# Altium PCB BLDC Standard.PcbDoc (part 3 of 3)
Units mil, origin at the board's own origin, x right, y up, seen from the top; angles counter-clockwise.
Board outline 4950 x 3000 mil, 4 copper layers (Top Layer, MidLayer1, MidLayer2, Bottom Layer), stack 63.4 mil thick; 211 components, 117 nets, 576 pads, 1027 vias.
Unrouted connection lines stored in the file: 2.
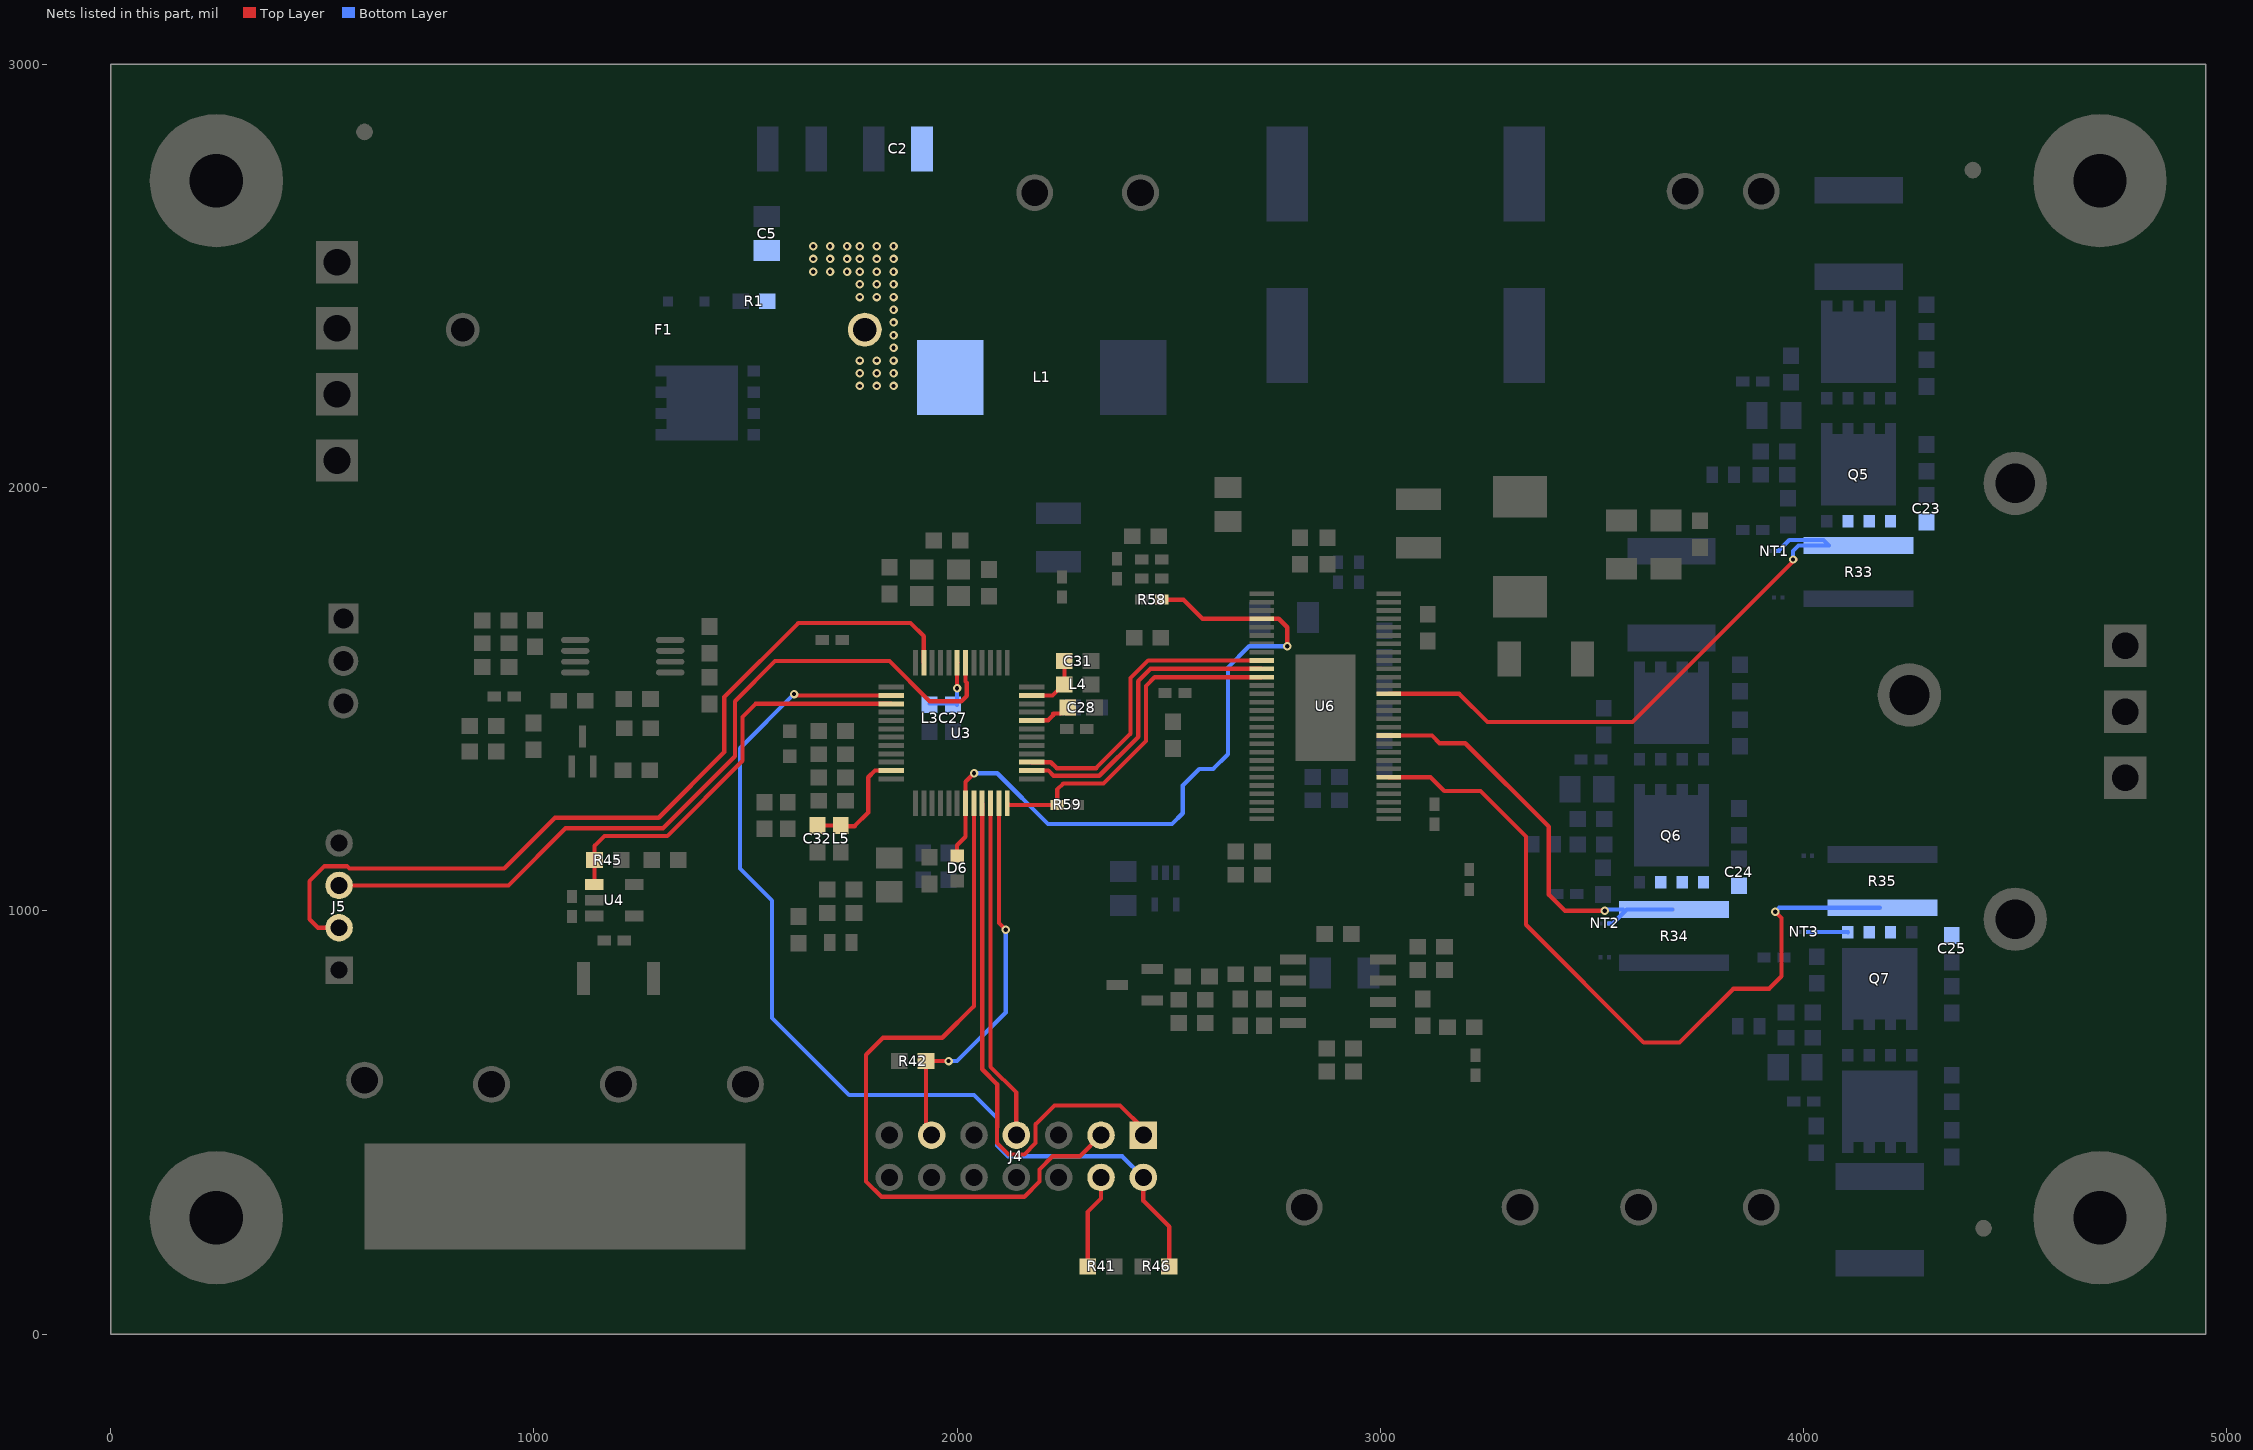
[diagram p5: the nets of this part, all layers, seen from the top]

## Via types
v1: diameter 20, hole 10, Top Layer to Bottom Layer, 1027 vias

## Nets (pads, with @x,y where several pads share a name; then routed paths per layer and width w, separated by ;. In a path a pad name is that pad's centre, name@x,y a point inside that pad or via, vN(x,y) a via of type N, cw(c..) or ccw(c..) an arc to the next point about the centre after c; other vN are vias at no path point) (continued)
PWRGD: D6.1 R58.1 U3.19 U6.4 | length 1702.5
  Top Layer w10: D6.1@2000,1129.53 2000,1155 2020,1175 U3.19@2020,1254 2020,1305 v1(2040,1325) ; R58.1@2483.62,1735 2535,1735 2580.09,1689.91 U6.4@2719.92,1689.91 2760.09,1689.91 2780,1670 v1(2780,1625)
  Bottom Layer w10: v1(2040,1325) 2095,1325 2215,1205 2507.53,1205 2533,1230.47 2533,1296 2572,1335 2605,1335 2640,1370 2640,1575 2690,1625 v1(2780,1625)
RESETN: R45.1 U3.3 U4.1 | length 991.6
  Top Layer w10: U4.1@1142.76,1062.4 1143.5,1063.15 R45.1@1143.5,1120 1143.5,1153.5 1167,1177 1315.46,1177 1493,1354.54 1493,1458 1524,1489 U3.3@1844.1,1489
SCIRXDA: J5.3 U3.42 | length 1902.6
  Top Layer w10: J5.3@540,1060 940,1060 1075,1195 1305,1195 1475,1365 1475,1495 1570,1590 1840,1590 1935,1495 2010,1495 2023,1508 2023,1538.55 2020,1541.55 U3.42@2020,1585.9
SCITXDA: J5.2 U3.47 | length 2028.8
  Top Layer w10: J5.2@540,960 490,960 470,980 470,1070 505.48,1105.48 558.84,1105.48 564.32,1100 930,1100 1050,1220 1295,1220 1450,1375 1450,1505 1625,1680 1890,1680 1921.5,1648.5 U3.47@1921.5,1585.9
SCLK: R59.2 U3.24 U6.11 | length 825.6
  Top Layer w10: U3.24@2118.5,1254 2122.5,1250 R59.2@2236.38,1250 2236.38,1286.38 2251,1301 2346,1301 2446,1401 2446,1531 2467.01,1552.01 U6.11@2719.92,1552.01
SDI: U3.27 U6.9 | length 732.1
  Top Layer w10: U3.27@2176.1,1351.1 2221.37,1351.1 2235.47,1337 2328.54,1337 2410,1418.46 2410,1550 2451.41,1591.41 U6.9@2719.92,1591.41
SDO: U3.26 U6.10 | length 730.7
  Top Layer w10: U3.26@2176.1,1331.4 2215.62,1331.4 2228.02,1319 2336,1319 2428,1411 2428,1542.54 2457.17,1571.71 U6.10@2719.92,1571.71
SL_A: C23.2 NT1.1 Q5.1 Q5.2 Q5.3 R33.2 U6.44 | length 1393.3
  Top Layer w10: U6.44@3019.92,1512.61 3186.48,1512.61 3253.09,1446 3596,1446 v1@3980,1830
  Bottom Layer w10: NT1.1@3940,1850 3966,1876 4046.99,1876 4060,1862.99 3987.99,1862.99 3975,1850 v1(3975,1830)
SL_B: C24.2 NT2.1 Q6.1 Q6.2 Q6.3 R34.2 U6.39 | length 983.5
  Top Layer w10: U6.39@3019.92,1414.11 3121.89,1414.11 3140,1396 3200.46,1396 3398,1198.46 3398,1038 3436,1000 v1(3530,1000)
  Bottom Layer w10: v1(3530,1000) 3532.99,1002.99 R34.2@3572.99,1002.99 ; NT2.1@3540,970 3549,970 3581.99,1002.99 R34.2@3690,1002.99
SL_C: C25.2 NT3.1 Q7.1 Q7.2 Q7.3 R35.2 U6.34 | length 1878.9
  Top Layer w10: U6.34@3019.92,1315.61 3118.39,1315.61 3151.04,1282.96 3236.59,1282.96 3344,1175.54 3344,967 3622,689 3706.98,689 3833.96,815.98 3918.51,815.98 3948,845.47 3948,983 v1(3933,998)
  Bottom Layer w10: v1(3933,998) 3942.01,1007.01 R35.2@4180,1007.01 ; NT3.1@4010,950 4103.81,950 Q7.1@4104.51,949.3
TCK: J4.11 R42.2 U3.23 | length 917.4
  Top Layer w10: J4.11@1940,470 1926.5,483.5 R42.2@1926.5,645 v1(1980,645) ; U3.23@2098.8,1254 2098.8,971.2 v1(2115,955)
  Bottom Layer w10: v1(1980,645) 2000,645 2115,760 v1(2115,955)
TDI: J4.3 U3.20 | length 1727.8
  Top Layer w10: U3.20@2039.7,1254 2039.7,774.7 1965,700 1825,700 1785,660 1785,360.68 1821.16,324.52 2158.84,324.52 2194.52,360.2 2194.52,388.84 2225.68,420 2290,420 J4.3@2340,470
TDIS: J4.4 R41.2 | length 223
  Top Layer w10: R41.2@2308.5,160 2308.5,288.5 2340,320 J4.4@2340,370
TDO: J4.7 U3.22 | length 809.2
  Top Layer w10: U3.22@2079.1,1254 2079.1,631.36 2140,570.46 J4.7@2140,470
TMS: J4.1 U3.21 | length 1285.9
  Top Layer w10: U3.21@2059.4,1254 2059.4,625.6 2095,590 2095,489.32 2094.52,488.84 2094.52,451.16 2121.16,424.52 2158.84,424.52 2185.48,451.16 2185.48,495.48 2230,540 2385,540 2440,485 J4.1@2440,470
TRSTN: J4.2 R46.2 U3.2 | length 2386.6
  Top Layer w10: v1(1615,1512) 1618.3,1508.7 U3.2@1844.1,1508.7 ; J4.2@2440,370 2440,315 2501.5,253.5 R46.2@2501.5,160
  Bottom Layer w10: v1(1615,1512) 1487,1384 1487,1100 1563,1024 1563,747 1745,565 2040,565 2094.52,510.48 2094.52,445.68 2120.2,420 2390,420 J4.2@2440,370
VBATT: C2.1 C5.1 F1.2 L1.1 R1.2
  other v1: 1770,2240 1810,2240 1850,2240 1770,2270 1810,2270 1850,2270 1770,2300 1810,2300 1850,2300 1850,2330 1850,2360 1850,2390 1850,2420 1770,2450 1810,2450 1850,2450 1770,2480 1810,2480 1850,2480 1660,2510 1700,2510 1740,2510 1770,2510 1810,2510 1850,2510 1660,2540 1700,2540 1740,2540 1770,2540 1810,2540 1850,2540 1660,2570 1700,2570 1740,2570 1770,2570 1810,2570 1850,2570
VDD: C28.1 U3.32 | length 93.3
  Top Layer w10: U3.32@2176.1,1449.6 2176.89,1450.39 2215.39,1450.39 2227,1462 ; 2227,1466 2244.5,1466 C28.1@2258.5,1480
VDD_1: C27.1 L3.2 U3.43 | length 164.5
  Top Layer w10: v1(2000,1526.02) 2000,1585.6 U3.43@2000.3,1585.9
  Bottom Layer w10: L3.2@1935,1489.45 C27.1@2000,1489.45 ; C27.1@2000,1486.5 C27.1@2000,1489.45 ; v1(2000,1526.02) C27.1@2000,1489.45
VDDA: C32.1 L5.2 U3.11 | length 266
  Top Layer w10: C32.1@1670,1201.5 L5.2@1725,1201.5 ; L5.2@1736.5,1200 1758,1200 1790,1232 1790,1315.54 1805.86,1331.4 U3.11@1844.1,1331.4
VDDIO_2: C31.1 L4.2 U3.35 | length 143.3
  Top Layer w10: U3.35@2176.1,1508.7 2225.43,1508.7 2251.73,1535 L4.2@2253.5,1535 C31.1@2253.5,1590
pads on no net: FID1.1 FID2.1 FID3.1 H1.0 H2.0 H3.1 H4.1 H5.0 H6.0 H7.1 H8.1 J4.6 J4.13 J4.14 LBL1.0 Logo1.0 U2.3 U3.30 U4.4 Y1.2 Y1.4

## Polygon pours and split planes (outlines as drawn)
3P3V on MidLayer2 "GND" (solid, remove dead copper, pour order 2): 450,1110 1000,1110 1000,300 2295,300 2300,305 2300,800 3150,800 3150,1930 450,1930
DC+ on MidLayer2 "GND" (solid, remove dead copper, pour order 8): 2532,2740 2296,2740 2296,2559 2085,2559 2085,1940 3160,1940 3160,180 3162.79,182.79 4427.21,182.79 4427.21,567.21 4430,570 4280,570 4280,630 4070,630 4070,720 3980,720 3980,860 4069.96,860 4069.96,929.96 4070,930 4380,930 4380,1138.71 4378.71,1140 3820,1140 3820,1080 3580,1080 3580,1040 3490,1040 3490,1389.8 3489.8,1390 3780,1390 3780,1550 3890,1550 3890,2060 4020,2060 4020,2237.57 4022.63,2240.2 4219.8,2240.2 4219.8,2399.8 4220,2400 4330,2400 4330,2570 2532,2570
GND on MidLayer1 "GND" (solid, remove dead copper, pour order 5): 20,2980 20,20 4930,20 4930,2980
GND on Bottom Layer "GND" (solid, remove dead copper, pour order 6): 20,2980 20,20 4930,20 4930,2980
DC+ on Bottom Layer "GND" (solid, remove dead copper, pour order 4): 2102.37,2770 2102.04,1962.15 3200,1960 3200,1237.8 2899,951.85 2899,190 4420,190 4420,440 4280,440 4280,630 4080,630 4080,450 3945,450 3690,705 3650,670 3470,850 3470,1390 3780,1390 3780,1550 3890,1550 3890,2290 4020,2290 4020,2240 4220,2240 4220,2400 4330,2400 4330,2570 2600,2570 2600,2770
GND on Top Layer "GND" (solid, remove dead copper, pour order 7): -57.39,2924.28 -57.39,-35.72 4852.61,-35.72 4852.61,2924.28

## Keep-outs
Keep-Out Layer:
  text ".Layer_Name" at 577,-858.49 h60

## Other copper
Top Layer:
  pour cut-out: 3635,580 3630,580 3630,587 3273,944 3273,950 3293,970 3622,641 3635,641
  region net VBATT: 1500,2590 1500,2510 1530,2510 1530,2420 1605,2420 1645,2380 1645,2160 2041,2160 2087,2206 2087,2720 1970,2720 1970,2870 1880,2870 1880,2592.44 1882.44,2590
  region net GND: 1485,2590 1235,2590 1235,2315 1495,2315 1495,2150 1600,2150 1600,2380 1375,2380 1375,2480 1485,2480
  region net NetF1_1: 480,2460 480,2160 1140,2160 1140,2530 840,2530 840,2460
  region net BATT_GND: 480,2480 820,2480 820,2550 1160,2550 1160,2140 480,2140 480,2000 1480,2000 1480,2290 1465,2305 1225,2305 1225,2600 1600,2600 1600,2870 1440,2870 1440,2710 480,2710
  pour cut-out: 1068.9,1380.1 1069,1380 1069,1360 1045,1360 1039,1366 1039,1394 1036,1394 1031,1399 1031,1420 1044,1420 1068.9,1444.9
  pour cut-out: 1985,1556 1970,1556 1970,1552 1912,1552 1911,1553 1910,1552 1910,1541 1941,1510 1985,1510
  pour cut-out: 1874.13,1713.39 1874,1713.25 1874,1700 1893,1700 1911.05,1681.95 1920.81,1681.95 1920.81,1704.88 1918.69,1707 1879,1707
  pour cut-out: 1701.81,1458.7 1701.81,1468.81 1702,1469 1702.45,1468.55 1745.22,1468.55 1745.22,1460.52 1743.4,1458.7
  pour cut-out: 1148.07,894.37 1150,896.3 1150,905 1140,905 1130,895
  pour cut-out: 1116.81,959.8 1116.81,936.46 1117.22,936.05 1121.16,940 1140,940 1140,960
  pour cut-out: 1275,1035 1275,1015 1220,1015 1220,1035
  pour cut-out: 585,1040 585,955 560,980 490,980 490,1055
  pour cut-out: 450,1135 450,1075 460,1075 510,1125 510,1135
  pour cut-out: 4285.79,628.34 4220,565 4285,565
  pour cut-out: 1900.44,427.82 1877.62,405 1807.07,405 1805.39,406.68 1805.39,433.32 1870.44,433.32 1881.55,444.43
  pour cut-out: 2487.48,517.48 2157.52,517.48 2155,520 2155,410 2175,390 2170,385 2170,305 2490,305
  pour cut-out: 3193.7,763.44 3277.72,763.44 3206.55,834.61 3186.18,834.61 3186.18,826.18 3193.7,826.18
  pour cut-out: 2839.21,758.19 2853.11,758.19 2853.11,788.05 2841.98,799.18 2840.84,798.03 2839.21,798.03
  pour cut-out: 3110,955 3080,985 2895,985 2895,965 3050,965 3050,955
  pour cut-out: 2934.61,1783.82 2908.7,1783.82 2910,1785.12 2910,1850 2940,1850
  pour cut-out: 3880,1780 3900,1780 3900,1770 3590,1460 3580,1470 3580,1480
  region net DGND: 2350,1640 2295,1640 2295,1570 2350,1570
  region net GND: 2830,750 2650,750 2650,670 2755,670 2755,710 2830,710
  region net GND: 2435,880 2435,825 2555,825 2550,830 2550,880
  region net 3P3V: 2910,965 2910,925 2955,925 2970,910 2970,870 3050,870 3050,965
  region net GND: 3775,1880 3710,1880 3710,1865 3515,1865 3515,1780 3730,1780 3760,1810 3775,1810
  region net 3P3V: 3610,1895 3250,1895 3170,1815 3015,1815 3015,1905 3150,1905 3165,1920 3165,2050 3610,2050
  region net GND: 2750,1222 2692,1222 2692,1070 2749.98,1070
  region net GND: 2435,1917 2360,1917 2360,1810 2455,1810 2455,1845 2435,1845
  region net GND: 1692.5,1445 1557.5,1445 1557.5,1405 1692.5,1405
  region net GND: 1870,1070 1805,1070 1805,985 1870,985
  region net 3P3V: 1715,945 1600,945 1600,880 1715,880
  region net GND: 1065,1570 1065,1530 1100,1530 1100,1440 1065,1440 1065,1380 1125,1380 1125,1450 1145,1450 1145,1570
  region net GND: 1330,880 1270,880 1270,800 1330,800
  region net 3P3V: 1300,1150 1180,1150 1180.16,1149.84 1180.16,1050 1300,1050
  region net C_PHASE: 4900,1380 4390,1380 4390,790 4300,790 4300,920 4080,920 4080,850 3990,850 3990,730 4080,730 4080,640 4230,640 4230,700 4306,700 4306,580 4900,580
  region net B_PHASE: 4900,1540 4400,1540 4400,1640 3900,1640 3900,1410 3790,1410 3790,1380 3640,1380 3640,1310 3570,1310 3570,1180 3500,1180 3500,1080 3560,1080 3560,1100 3797.83,1100 3797.83,1210 4370,1210 4370,1400 4900,1400
  region net A_PHASE: 4080,2230 4080,2160 4030,2160 4030,2050 3940,2050 3940,1950 4230,1950 4230,2070 4340,2070 4340,1660 4420,1660 4420,1560 4900,1560 4900,2230 4370,2230 4370,2260 4230,2260 4230,2230
  region net NetC43_1: 3087,1660 3087,1620 3270,1620 3270,1555 3370,1555 3370,1800 3250,1800 3250,1660
  region net DC+: 3630,1970 3630,1890 3780,1890 3780,1970
  region net DC+: 3057,1720 3075,1720 3075,1695 3065,1685 3057,1685
  text ".CopyrightYear" at 532,90 h60
  text "TI" at 808,90 h60
  text "©" at 414,83 h105
  text ".Layer_Name" at 577,-858.49 h60
MidLayer1:
  text ".Layer_Name" at 577,-858.49 h60
MidLayer2:
  region net DGND: 2032.35,1499.43 1955,1499.43 1955,1380 2195,1380 2195,1495 2295,1495 2295,1460 2365,1460 2365,1475 2390,1475 2390,1515 2335,1515 2335,1555 2355,1555 2355,1635 2170,1635 2170,1515 2155,1500 2045,1500
  region net C_PHASE: 4900,1380 4390,1380 4390,790 4300,790 4300,920 4080,920 4080,850 3990,850 3990,730 4080,730 4080,640 4230,640 4230,700 4306,700 4306,580 4900,580
  region net B_PHASE: 4900,1540 4400,1540 4400,1640 3900,1640 3900,1410 3790,1410 3790,1380 3640,1380 3640,1310 3570,1310 3570,1180 3500,1180 3500,1080 3560,1080 3560,1100 3797.83,1100 3797.83,1210 4370,1210 4370,1400 4900,1400
  region net A_PHASE: 4080,2230 4080,2160 4030,2160 4030,2050 3940,2050 3940,1950 4230,1950 4230,2070 4340,2070 4340,1660 4420,1660 4420,1560 4900,1560 4900,2230 4370,2230 4370,2260 4230,2260 4230,2230
  text ".Layer_Name" at 577,-858.49 h60
Bottom Layer:
  region net VBATT: 1500,2590 1500,2510 1530,2510 1530,2420 1605,2420 1645,2380 1645,2160 2041,2160 2087,2206 2087,2720 1970,2720 1970,2870 1880,2870 1880,2592.44 1882.44,2590
  region net BATT_GND: 480,2480 820,2480 820,2550 1160,2550 1160,2140 480,2140 480,2000 1480,2000 1480,2290 1465,2305 1225,2305 1225,2600 1600,2600 1600,2870 1440,2870 1440,2710 480,2710
  region net DC+: 880,1400 880,1330 1050,1330 1050,1400
  region net NetF1_1: 480,2460 480,2160 1140,2160 1140,2530 840,2530 840,2460
  region net GND: 4265,2800 3800,2800 3800,2600 4265,2600
  region net GND: 4290,210 4060,210 4060,70 4290,70
  region net GND: 4270,1790 4000,1790 4000,1665 4270,1665
  region net GND: 4045,1200 4045,1070 4375,1070 4375,1200
  region net GND: 3555,935 3555,810 3770,810 3785,825 3785,835 3830,835 3830,935
  region net GND: 2105,2595 2105,2945 3600,2945 3600,2600 2520,2600 2520,2805 2305,2805 2305,2595
  region net GND: 2890,965 2845,965 2845,895 2825,895 2825,815 2890,815
  region net GND: 2500,1107.56 2427.32,1107.56 2427.32,1117.56 2337.32,1117.56 2337.32,1067.56 2432.32,1067.56 2432.32,1072.56 2500,1072.56
  region net GND: 2293.15,1861 2183.15,1861 2183.15,1786 2293.15,1786
  region net GND: 1485,2590 1235,2590 1235,2315 1495,2315 1495,2150 1600,2150 1600,2380 1375,2380 1375,2480 1485,2480
  region net C_PHASE: 4900,1380 4390,1380 4390,790 4300,790 4300,920 4080,920 4080,850 3990,850 3990,730 4080,730 4080,640 4230,640 4230,700 4306,700 4306,580 4900,580
  region net B_PHASE: 4900,1540 4400,1540 4400,1640 3900,1640 3900,1410 3790,1410 3790,1380 3640,1380 3640,1310 3570,1310 3570,1180 3500,1180 3500,1080 3560,1080 3560,1100 3797.83,1100 3797.83,1210 4370,1210 4370,1400 4900,1400
  region net A_PHASE: 4080,2230 4080,2160 4030,2160 4030,2050 3940,2050 3940,1950 4230,1950 4230,2070 4340,2070 4340,1660 4420,1660 4420,1560 4900,1560 4900,2230 4370,2230 4370,2260 4230,2260 4230,2230
  region net 3P3V: 2322.32,1047.56 2322.32,987.56 2532.32,987.56 2532.32,1047.56
  region net SL_A: 4310,1940 4080,1940 4080,1890 4000,1890 4000,1820 4310,1820
  region net NetC2_2: 1630,2870 1630,2660 1840,2660 1840,2870
  region net SL_C: 4370,920 4370,1040 4040,1040 4040,930 4220,930 4220,980 4320,980 4320,920
  region net B_V_ADC: 3490,1320 3490,1140 3400,1140 3400,1290 3430,1320
  region net NetC12_2: 3500,1440 3500,1340 3630,1340 3630,1370 3560,1370 3560,1440
  region net SL_B: 3640,1090 3870,1090 3870,980 3566.05,980 3566.05,1023 3640,1023
  region net C_V_ADC: 3977,783 3977,593 3877,593 3877,783
  text ".VersionControl_RevNumber" at 1970,170 h60
  text "MADE IN U.S." at 1967,111 h60
  text "UL94V-0" at 1605,110 h60
  text "SVN:" at 1970,54 h60
  text ".Layer_Name" at 577,-858.49 h60

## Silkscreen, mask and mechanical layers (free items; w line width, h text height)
Top Overlay:
  text "A VOLT" at 3613,2782 h60
  text "DC+" at 2397,2780 h60
  text "GND" at 3852,2780 h60
  text "GND" at 2126,2779 h60
  text "GND" at 550,680 h60
  text "B CURR" at 800,670 h60
  text "DC VOLT" at 1100,670 h60
  text "A CURR" at 1400,670 h60
  text "ADC REF" at 2710,380 h60
  text "C CURR" at 3230,380 h60
  text "B VOLT" at 3510,380 h60
  text "C VOLT" at 3810,380 h60
  text ".Layer_Name" at 577,-858.49 h60
Bottom Overlay:
  region: 65,1691 65,1391 165,1391 165,1691
  text ".PRJ_Number" at 75,725 h60 r270
  text ".PCB_Rev" at 175,725 h60 r270
  text ".Layer_Name" at 577,-858.49 h60
Top Paste:
  text ".Layer_Name" at 577,-858.49 h60
Bottom Paste:
  text ".Layer_Name" at 577,-858.49 h60
Top Solder:
  text ".Layer_Name" at 577,-858.49 h60
  text ".Layer_Name" at 577,-858.49 h60
Bottom Solder:
  text ".Layer_Name" at 577,-858.49 h60
Drill Guide:
  text ".Layer_Name" at 577,-858.49 h60
M1 Board Outline:
  the board outline again, w10
  text ".Layer_Name" at 577,-858.49 h60
M2 Board Dimensions:
  rectangle: 124.5,-410.5 499.5,-285.5
  rectangle: -0.5,-285.5 124.5,-160.5
  lines w7: -0.5,-285.5 999.5,-285.5 ; 124.5,-410.5 124.5,-160.5 ; 249.5,-410.5 249.5,-160.5 ; 499.5,-410.5 499.5,-160.5 ; 749.5,-410.5 749.5,-160.5 ; -0.5,-410.5 -0.5,-160.5 999.5,-160.5 999.5,-410.5 -0.5,-410.5
  lines w10: -0.5,-475.5 -0.5,-455.5 ; 59.5,-485.5 -0.5,-465.5 ; 59.5,-445.5 -0.5,-465.5 ; 223.58,-465.5 -0.5,-465.5 ; 775.42,-465.5 999.5,-465.5 ; 939.5,-485.5 999.5,-465.5 ; 939.5,-445.5 999.5,-465.5 ; 999.5,-475.5 999.5,-455.5
  text "1000 (mil)" at 233.58,-501.49 h60
  text ".Layer_Name" at 577,-858.49 h60
M3 3D STEP Top:
  text ".Layer_Name" at 577,-858.49 h60
M4 3D STEP Bottom:
  text ".Layer_Name" at 577,-858.49 h60
M5 Assembly Top:
  lines w10: -292,-930.17 6308,-930.17 ; -292,-726.83 6310,-726.83 ; -292,-523.5 -292,-1133.5 3713,-1133.5 6310,-1133.5 6310,-523.5 -291.5,-523.5 -291.5,-1133.5 1284,-1133.5 ; 2173,-1133.5 2173,-523.5 ; 3440,-726.83 3440,-523.5 ; 4280,-726.83 4280,-523.5 ; 4902,-1140 4902,-937.17
  text "COMPONENTS MARKED 'DNP' SHOULD NOT BE POPULATED." at 1153.5,-318.5 h60
  text "ASSEMBLY VARIANT:" at 1153,-434 h60
  text ".VariantName" at 2189,-434 h60
  text "PCB VIEWED FROM TOP SIDE" at -228.5,-655.67 h60
  text "BOARD #:" at 2248,-655.67 h60
  text ".PRJ_Number" at 2793.5,-655.67 h60
  text "REV:" at 3638,-655.67 h60
  text ".PCB_Rev" at 3929.5,-655.67 h60
  text "SVN REV:" at 4476,-655.67 h60
  text ".VersionControl_RevNumber" at 4982,-655.67 h60
  text "IGNORE ->" at -228.5,-858.49 h60
  text "PLOT NAME =" at -228.5,-1064.34 h60
  text ".plot_File_Name" at 577,-1064.34 h60
  text "GENERATED    :" at 2250,-1064.34 h60
  text ".Print_Date" at 3119.5,-1064.34 h60
  text ".Print_Time" at 3848.5,-1064.34 h60
  text "TEXAS INSTRUMENTS" at 5113,-1064.34 h60
M6 Assembly Bottom:
  lines w10: -292.5,-727.33 6309.5,-727.33 ; -290.5,-930.67 6309.5,-930.67 ; 1115.5,-1140.5 1115.5,-937.67 ; 1737.5,-727.33 1737.5,-524 ; 2577.5,-727.33 2577.5,-524 ; 3844.5,-1134 3844.5,-524 ; 4733.5,-1134 6309,-1134 6309,-524 -292.5,-524 -292.5,-1134 2304.5,-1134 6309.5,-1134 6309.5,-524
  text "COMPONENTS MARKED 'DNP' SHOULD NOT BE POPULATED." at 6102,-318 h60
  text ".VariantName" at 5058,-434 h60
  text "ASSEMBLY VARIANT:" at 6097,-434 h60
  text ".VersionControl_RevNumber" at 1035.5,-656.17 h60
  text "SVN REV:" at 1541.5,-656.17 h60
  text ".PCB_Rev" at 2088,-656.17 h60
  text "REV:" at 2379.5,-656.17 h60
  text ".PRJ_Number" at 3224,-656.17 h60
  text "BOARD #:" at 3769.5,-656.17 h60
  text "PCB VIEWED FROM BOTTOM SIDE" at 6246,-656.17 h60
  text "IGNORE ->" at 2547.85,-858.49 h60
  text "TEXAS INSTRUMENTS" at 904.5,-1064.84 h60
  text ".Print_Time" at 2169,-1064.84 h60
  text ".Print_Date" at 2898,-1064.84 h60
  text "GENERATED    :" at 3767.5,-1064.84 h60
  text ".plot_File_Name" at 5440.5,-1064.84 h60
  text "PLOT NAME =" at 6246,-1064.84 h60
M9 Title Sheet:
  drawing of 55 lines, arcs and shapes, not listed
  text "1" at 739.84,8036.5 h70
  text "2" at 3235.5,8036.5 h70
  text "3" at 5724.84,8036.5 h70
  text "4" at 8231.51,8036.5 h70
  text "5" at 10730.5,8036.5 h70
  text "6" at 13235.5,8036.5 h70
  text "A" at -416.5,6893.5 h70
  text "A" at 14383.5,6893.5 h70
  text "B" at -416.5,4513.5 h70
  text "B" at 14383.5,4513.5 h70
  text "C" at -416.5,2138.5 h70
  text "PROJECT TITLE:" at 11340,290 h45
  text ".PRJ_Title" at 11393.5,144.17 h70
  text "DESIGNED FOR:" at 11343.5,-23.5 h45
  text ".PRJ_Customer" at 11393.5,-163.5 h70
  text "D" at -416.5,-231.5 h70
  text "D" at 14383.5,-231.5 h70
  text "FILE NAME:" at 11343.5,-323.5 h45
  text ".PCB_File_Name_No_Path" at 11393.5,-443.5 h70
  text "Texas Instruments (TI) and/or its licensors do not warrant the accuracy or completeness of this specification" at 6374,-605.34 h45
  text "ENGINEER:" at 11343.5,-613.5 h45
  text "LAYOUT BY:" at 12848.5,-613.5 h45
  text "or any information contained therein. TI and/or its licensors do not warrant that this design will meet" at 6329.01,-718 h45
  text ".PRJ_Engineer" at 11393.5,-768.49 h70
  text ".PCB_Layout" at 12899,-768.49 h70
  text "the specifications, will be suitable for your application or fit for any particular purpose, or will operate in" at 6329.01,-830.67 h45
  text ".Layer_Name" at 577,-858.49 h60
  text "ALTIUM DESIGNER VERSION:" at 12848.5,-923.5 h45
  text "an implementation. TI and/or its licensors do not warrant that the design is production worthy. You should" at 6329.01,-943.33 h45
  text "completely validate and test your design implementation to confirm the system functionality for your application." at 6374,-1056 h45
  text ".print_Scale" at 11393.5,-1056.83 h70
  text ".Application_BuildNumber" at 12899,-1056.83 h70
  text "1" at 739.84,-1263.5 h70
  text "2" at 3235.5,-1263.5 h70
  text "3" at 5724.84,-1263.5 h70
  text "4" at 8231.51,-1263.5 h70
  text "5" at 10730.5,-1263.5 h70
  text "6" at 13235.5,-1263.5 h70
M10 Fab Notes:
  drawing of 203 lines, arcs and shapes, not listed
  text "DESIGN INFORMATION" at 12377.02,6803 h60
  text "(REFER ALSO ARRAY/PANEL PROFILING INFORMATION)" at 12015.46,6641.29 h60
  text "BOARD SIZE" at 11329.46,6637 h60
  text "3450MIL" at 11791.78,6509.18 h60
  text "X" at 12297.46,6509.18 h60
  text "4950MIL" at 12528.78,6509.18 h60
  text "Number of Layers :" at 11732.46,6312 h60
  text "4" at 12827.27,6302 h60
  text "MIN. TRACK WIDTH:" at 11732.46,6173 h60
  text "8" at 12828.7,6173 h60
  text "MIL" at 12983.46,6173 h60
  text "MIN. CLEARANCE:" at 11732.46,6041 h60
  text "8" at 12828.7,6041 h60
  text "MIL" at 12983.46,6041 h60
  text "MIN. VIA PAD SIZE:" at 11732.46,5909 h60
  text "20" at 12798.71,5909 h60
  text "MIL" at 12983.46,5909 h60
  text "0.05mm (2MIL)" at 12427.46,5767.29 h60
  text "MINIMUM ANNULAR RING" at 11403.23,5763 h60
  text "EXTERNAL" at 13135.46,5763 h60
  text "PER" at 11603.23,5645 h60
  text "IPC-D-275 CLASS 2 LEVEL C" at 11823.23,5645 h60
  text "MIL, HOLES" at 13311.46,5532.71 h60
  text "+/-" at 12919,5532 h60
  text "+/-" at 13773,5532 h60
  text "REGISTRATION TOLERANCES:" at 11403.23,5527 h60
  text "METAL" at 12603,5527 h60
  text "5" at 13179.2,5527 h60
  text "3" at 14012.2,5527 h60
  text "MIL" at 14128.46,5527 h60
  text "MATERIAL:" at 11328.46,5317.54 h60
  text "FR-4 High Tg" at 12314.9,5177.21 h60
  text "FR-4" at 11789.46,5168.64 h60
  text "X" at 12161.46,5168.64 h60
  text "OTHER" at 13237.46,5168.64 h60
  text "62 MIL (1.6mm) +/-10%" at 12069.56,5005.92 h60
  text "THICKNESS:" at 11403.23,5001.64 h60
  text "X" at 11941.4,5001.64 h60
  text "OTHER" at 13354.46,5001.64 h60
  text "TOLERANCE:" at 11403.23,4843.64 h60
  text "X" at 12242.53,4843.64 h60
  text "ANSI IPC-6012 TYPE 3 CLASS 2" at 12429.48,4843.64 h60
  text "OTHER +/-" at 12429.46,4687.64 h60
  text "BOW & TWIST:" at 11403.23,4530.64 h60
  text "X" at 12242.53,4530.64 h60
  text "ANSI IPC-6012 TYPE 3 CLASS 2" at 12429.48,4530.64 h60
  text "OTHER +/-" at 12429.46,4372.13 h60
  text "COPPER THICKNESS (FINISHED):" at 11328.46,4236.64 h60
  text "1.4MIL (1oz)" at 12208.46,4083.92 h60
  text "2MIL (1.4oz)" at 12975.46,4083.92 h60
  text "2.8MIL (2oz)" at 13702.46,4083.92 h60
  text "OUTER:" at 11685.46,4079.64 h60
  text "X" at 13565,4075 h60
  text "X" at 13267,3928 h60
  text "1.4MIL (1oz)" at 12558.46,3926.92 h60
  text "2.8MIL (2oz)" at 13402.46,3926.92 h60
  text "INNER SIGNAL:" at 11685.46,3922.64 h60
  text "DRILLING:" at 11328.46,3783.64 h60
  text "REFERENCE:" at 11403.23,3666.64 h60
  text "X" at 12051.46,3666.64 h60
  text "AS SHOWN" at 12238.46,3666.64 h60
  text "X" at 12952.46,3666.64 h60
  text "NC_DRILL FILES" at 13089.46,3666.64 h60
  text "PTH MIN COPPER THICKNESS:" at 11403.23,3508.64 h60
  text "X" at 12753.46,3508.64 h60
  text "1MIL" at 12890.46,3508.64 h60
  text "OTHER" at 13387.46,3508.64 h60
  text "BOARD FINISH:" at 11328.46,3349.64 h60
  text "SILKSCREEN:" at 11483.68,3231.64 h60
  text "X" at 12432.46,3231.64 h60
  text "TOP" at 12558.46,3231.64 h60
  text "X" at 12942.46,3231.64 h60
  text "BOTTOM" at 13069.46,3231.64 h60
  text "SILKSCREEN COLOR:" at 11483.68,3064.64 h60
  text "X" at 12431.42,3064.64 h60
  text "WHITE" at 12558.46,3064.64 h60
  text "OTHER" at 13069.46,3064.64 h60
  text "SOLDER RESIST COLOR:" at 11483.68,2894.64 h60
  text "X" at 12051.42,2735.44 h60
  text "GREEN" at 12178.46,2735.44 h60
  text "BLUE" at 12769.46,2735.44 h60
  text "OTHER" at 13307.46,2735.44 h60
  text "IMMERSION GOLD (ENIG)" at 12389.46,2546.92 h60
  text "SURFACE FINISH:" at 11328.46,2542.64 h60
  text "X" at 12202.51,2542.64 h60
  text "Pb-FREE HASL" at 13621.75,2542.64 h60
  text "OTHER" at 12389.46,2385.64 h60
  text "ARRAY/PANEL:" at 11328.46,2206.64 h60
  text "CUT AND TRIM PER MECH LAYER 1" at 12389.46,2202.35 h60
  text "N.C. ROUTE" at 12389.46,2050.64 h60
  text "X" at 13068.46,2050.64 h60
  text "V. SCORE" at 13255.46,2050.64 h60
  text "CERTIFICATION:" at 11328.46,1913.64 h60
  text "MATERIALS AND WORKMANSHIP FOR ALL PCBS" at 12053.46,1913.64 h60
  text "TO MEET OR EXCEED THE REQUIREMENTS OF:" at 12053.46,1815.64 h60
  text "X" at 11679.96,1679.13 h60
  text "ANSI IPC-A-600F CLASS ->" at 11818.96,1679.13 h60
  text "X" at 13458.02,1679.13 h60
  text "2" at 13576.96,1679.14 h60
  text "1" at 13261.96,1677.64 h60
  text "3" at 13930.96,1677.64 h60
  text "X" at 11682.02,1519.64 h60
  text "UL 94V-0" at 11818.96,1519.64 h60
  text "X" at 12494.02,1519.64 h60
  text "RoHS" at 12630.96,1519.64 h60
  text "OTHER" at 13275.36,1519.64 h60
  text "PER ORDER" at 13672.42,1519.64 h60
  text "ADDITIONAL REQUIREMENTS:" at 11328.46,1378.64 h60
  text "MICROSECTION:" at 11403.23,1263.64 h60
  text "YES" at 12308.96,1263.64 h60
  text "REQUIRED" at 13170.46,1107.49 h60
  text "BARE BOARD ELEC. TEST:" at 11403.23,1104.64 h60
  text "NONE" at 12708.96,1104.64 h60
  text "X" at 13043.46,1104.64 h60
  text "PER ORDER" at 13762.46,1104.64 h60
  text "MANUFACTURER'S ID/LOGO:" at 11403.23,947.64 h60
  text "RAIL" at 12868.96,943.35 h60
  text "X" at 13243.46,943.35 h60
  text "METAL" at 13360.77,943.35 h60
  text "SILK" at 13872.46,943.35 h60
  text ".Layer_Name" at 577,-858.49 h60
M11 Gerber Information:
  lines w10: -292,-930.17 6308,-930.17 ; -292,-726.83 6310,-726.83 ; -292,-523.5 -292,-1133.5 3713,-1133.5 6310,-1133.5 6310,-523.5 -291.5,-523.5 -291.5,-1133.5 1284,-1133.5 ; 2173,-1133.5 2173,-523.5 ; 3440,-726.83 3440,-523.5 ; 4280,-726.83 4280,-523.5 ; 4902,-1140 4902,-937.17
  text "ALL ARTWORK VIEWED FROM TOP SIDE" at -228.5,-655.67 h60
  text "BOARD #:" at 2248,-655.67 h60
  text ".PRJ_Number" at 2793.5,-655.67 h60
  text "REV:" at 3638,-655.67 h60
  text ".PCB_Rev" at 3929.5,-655.67 h60
  text "SVN REV:" at 4476,-655.67 h60
  text ".VersionControl_RevNumber" at 4982,-655.67 h60
  text "LAYER NAME =" at -228.5,-858.49 h60
  text "PLOT NAME =" at -228.5,-1064.34 h60
  text ".plot_File_Name" at 577,-1064.34 h60
  text "GENERATED    :" at 2250,-1064.34 h60
  text ".Print_Date" at 3119.5,-1064.34 h60
  text ".Print_Time" at 3848.5,-1064.34 h60
  text "TEXAS INSTRUMENTS" at 5113,-1064.34 h60
M12 Stackup:
  lines w6: 11199,7699.25 14235,7699.25 ; 11199,7803.65 14235,7803.65 ; 11139,6951 ccw(c11173,6951) 11173,6917 14261,6917 ccw(c14261,6951) 14295,6951 14295,7922 ccw(c14261,7922) 14261,7956 11173,7956 ccw(c11173,7922) 11139,7922 11139,6951
  text "Layer Stack Up Detail for: BLDC Standard.PcbDoc" at 11199,7835.62 h59
  text "Layer" at 11199,7764.65 h24
  text "Gerber" at 11852.81,7764.65 h24
  text "Copper" at 12174.33,7764.65 h24
  text "Dielectric" at 12535.04,7764.65 h24
  text "Dielectric" at 12912.54,7764.65 h24
  text "Dielectric" at 13396.41,7764.65 h24
  text "Dielectric" at 13773.91,7764.65 h24
  text "Name" at 11199,7716.65 h24
  text "Document" at 11852.81,7716.65 h24
  text "Thickness" at 12174.33,7716.65 h24
  text "Height" at 12535.04,7716.65 h24
  text "Material" at 12912.54,7716.65 h24
  text "Constant" at 13396.41,7716.65 h24
  text "Type" at 13773.91,7716.65 h24
  text "Top Solder Mask" at 11199,7642.14 h34
  text "(.GTS)" at 11852.81,7642.14 h34
  text "0.4mil" at 12535.04,7642.14 h34
  text "Solder Resist" at 12912.54,7642.14 h34
  text "3.50" at 13396.41,7642.14 h34
  text "Top Layer" at 11199,7533.91 h34
  text "(.GTL)" at 11852.81,7533.91 h34
  text "1.4mil" at 12174.33,7533.91 h34
  text "12.6mil" at 12535.04,7479.79 h34
  text "370HR" at 12912.54,7479.79 h34
  text "4.80" at 13396.41,7479.79 h34
  text "PrePreg" at 13773.91,7479.79 h34
  text "MidLayer1" at 11199,7425.68 h34
  text "(.G1)" at 11852.81,7425.68 h34
  text "1.4mil" at 12174.33,7425.68 h34
  text "32.6mil" at 12535.04,7371.56 h34
  text "370HR" at 12912.54,7371.56 h34
  text "4.80" at 13396.41,7371.56 h34
  text "Core" at 13773.91,7371.56 h34
  text "MidLayer2" at 11199,7317.45 h34
  text "(.G2)" at 11852.81,7317.45 h34
  text "1.4mil" at 12174.33,7317.45 h34
  text "12.6mil" at 12535.04,7263.33 h34
  text "370HR" at 12912.54,7263.33 h34
  text "4.80" at 13396.41,7263.33 h34
  text "PrePreg" at 13773.91,7263.33 h34
  text "Bottom Layer" at 11199,7209.22 h34
  text "(.GBL)" at 11852.81,7209.22 h34
  text "1.4mil" at 12174.33,7209.22 h34
  text "Bottom Solder Mask" at 11199,7100.99 h34
  text "(.GBS)" at 11852.81,7100.99 h34
  text "0.4mil" at 12535.04,7100.99 h34
  text "Solder Resist" at 12912.54,7100.99 h34
  text "3.50" at 13396.41,7100.99 h34
  text ".Layer_Name" at 577,-858.49 h60
M13 Component Bodies Top:
  text ".Layer_Name" at 577,-858.49 h60
M14 Component Bodies Bottom:
  text ".Layer_Name" at 577,-858.49 h60
M15 Courtyards Top:
  text ".Layer_Name" at 577,-858.49 h60
M16 Courtyards Bottom:
  text ".Layer_Name" at 577,-858.49 h60
Drill Drawing:
  text ".legend" at 5349.5,806.5 h60
  text "Drill Table" at 5374.5,621.5 h60
  text ".Layer_Name" at 577,-858.49 h60

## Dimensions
0,0 to 4950,0 on M2 Board Dimensions
0,0 to 0,3000 on M2 Board Dimensions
